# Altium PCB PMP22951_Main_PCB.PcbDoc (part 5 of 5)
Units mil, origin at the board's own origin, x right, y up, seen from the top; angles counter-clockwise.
Board outline 6643.5 x 4153.54 mil, 6 copper layers (Top Layer, Signal Layer 1, Signal Layer 2, Signal Layer 3, Signal Layer 4, Bottom Layer), stack 65.8 mil thick; 139 components, 80 nets, 687 pads, 417 vias.
Unrouted connection lines stored in the file: 2.
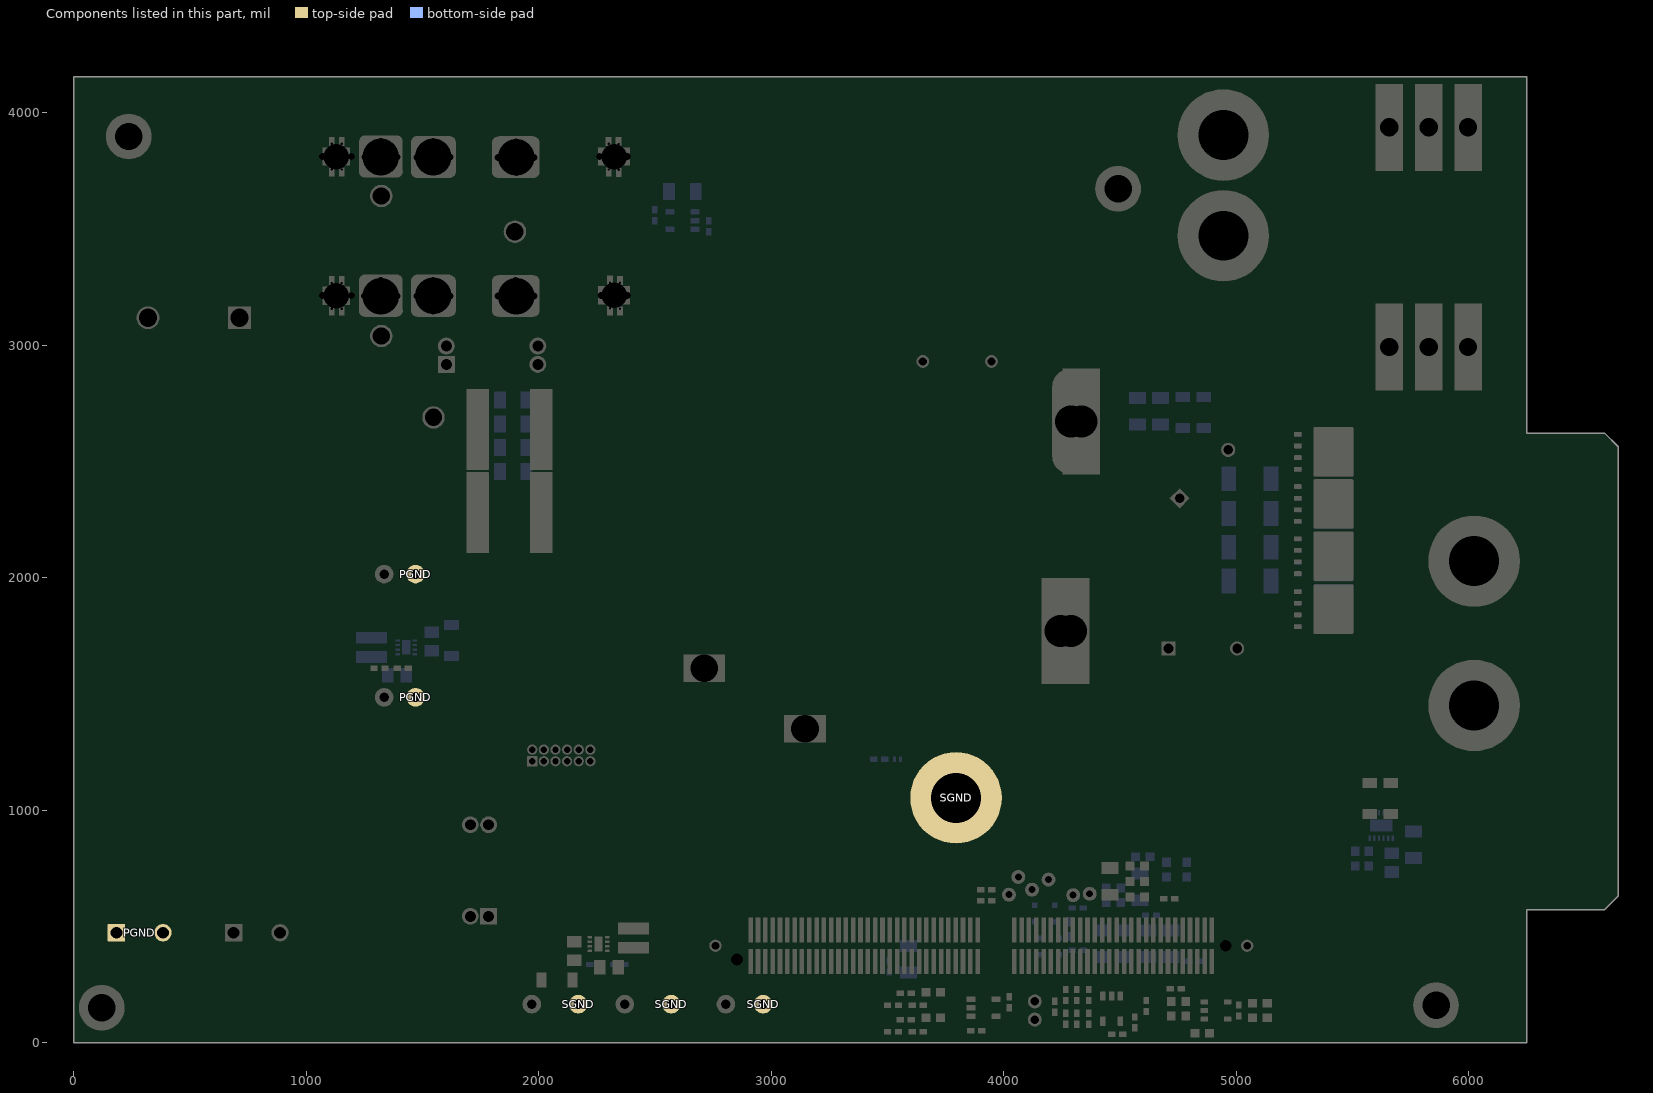
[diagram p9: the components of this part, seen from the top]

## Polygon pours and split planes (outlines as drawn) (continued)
SWNODE2 on Signal Layer 2 "SWNODE2" (solid, remove dead copper, pour order 752): 1236.22,3307.09 1220.47,3291.34 1220.47,3039.37 1283.46,2976.38 1354.33,2976.38 1417.32,3039.37 1417.32,3291.34 1401.57,3307.09
SWNODE1 on Signal Layer 2 "SWNODE1" (solid, remove dead copper, pour order 740): 1236.22,3913.39 1220.47,3897.64 1220.47,3645.67 1283.46,3582.68 1354.33,3582.68 1417.32,3645.67 1417.32,3897.64 1401.57,3913.39
VBB1 on Signal Layer 2 "VBB1" (solid, remove dead copper, pour order 728): 1811.02,3917.32 1771.65,3877.95 1771.65,3141.73 1811.02,3102.36 1984.25,3102.36 2023.62,3141.73 2023.62,3877.95 1984.25,3917.32
SWNODE3 on Signal Layer 2 "SWNODE3" (solid, remove dead copper, pour order 704): 5546.38,4123.43 5561.38,4138.43 5711.38,4138.43 5726.38,4123.43 5726.38,3553.43 5906.38,3373.43 5906.38,2818.43 5886.38,2798.43 5776.38,2798.43 5756.38,2818.43 5756.38,3243.62 5546.38,3453.62
SWNODE4 on Signal Layer 2 "SWNODE4" (solid, remove dead copper, pour order 702): 5921.38,4123.43 5906.38,4138.43 5756.38,4138.43 5741.38,4123.43 5741.38,3563.43 5921.38,3383.43 5921.38,2818.43 5941.38,2798.43 6056.38,2798.43 6076.38,2818.43 6076.38,3593.43 5921.38,3748.43
SWNODE4 on Signal Layer 2 "SWNODE4" (solid, remove dead copper, pour order 700): 5726.38,3177.17 5724.41,3179.13 5724.41,3255.91 5531.5,3448.82 5531.5,3566.93 5433.07,3665.35 4771.65,3665.35 4748.03,3641.73 4748.03,3299.21 4771.65,3275.59 5326.77,3275.59 5338.58,3263.78 5338.58,3050.65 5605.56,2783.43 5706.38,2783.43 5726.38,2803.43
VSR on Signal Layer 2 "VSR" (solid, remove dead copper, pour order 630): 3335,2050 3160,1875 3160,1445 3170,1435 4250,1435 4409.45,1594.45 4409.45,2007.87 4367.32,2050
Iout_SNS on Signal Layer 2 "Iout_SNS" (solid, remove dead copper, pour order 626): 4854.33,2488.19 4905.51,2488.19 4929.13,2464.57 4929.13,1858.27 4724.41,1653.54 4645.67,1653.54 4515.75,1783.46 4515.75,2062.99 4334.65,2244.09 4114.17,2464.57 4114.17,2759.84 4259.84,2905.51 4437.01,2905.51
SGND on Signal Layer 2 "SGND" (solid, remove dead copper, pour order 256): 4860,1095 4880,1075 5134.06,1075 5444.88,1385.83 5500,1385.83 5500,1708.66 5452.76,1708.66 5417.32,1744.09 5125.98,1744.09 5102.36,1767.72 5102.36,2586.61 5047.24,2641.73 4905.51,2641.73 4885.83,2622.05 4885.83,2527.56 4940.94,2472.44 4940.94,1854.33 4860,1773.39
54V1 on Signal Layer 2 "54V1" (solid, remove dead copper, pour order 156): 5122.05,2633.86 5110.24,2622.05 5110.24,1779.53 5129.92,1759.84 5267.72,1759.84 5287.4,1779.53 5287.4,2622.05 5275.59,2633.86
54V2 on Signal Layer 2 "54V2" (solid, remove dead copper, pour order 140): 6228.35,1759.84 6244.09,1775.59 6244.09,2645.67 6224.41,2665.35 5350.39,2665.35 5330.71,2645.67 5330.71,1779.53 5350.39,1759.84
SGND on Signal Layer 2 "SGND" (solid, remove dead copper, pour order 586): 2299.21,1248.03 3515.75,1248.03 3574.8,1188.98 3574.8,755.91 3940.94,755.91 4244.09,1059.05 6192.91,1059.06 6232.28,1019.68 6232.28,35.43 6196.85,0 1910,0 1586.61,0 1559.06,31.5 1559.05,980.32 1724.41,1145.67 1925.2,1346.46 2200.79,1346.46
SGND on Signal Layer 2 "SGND" (solid, remove dead copper, pour order 616): 4255.91,1417.32 4055.12,1417.32 4043.31,1405.51 4043.31,1291.34 4035.43,1283.46 2255.91,1283.46 2255.91,775.59 3937.01,775.59 4240.16,1078.74 4901.57,1078.74 4901.57,1779.53 4889.76,1779.53 4755.91,1645.67 4484.25,1645.67
PGND on Signal Layer 3 "PGND" (solid, remove dead copper, pour order 766): 1062.99,3346.46 944.88,3228.35 633.86,3228.35 606.3,3200.79 606.3,736.22 531.5,661.42 531.5,492.13 433.07,393.7 137.8,393.7 39.37,492.13 39.37,3440.94 145.67,3547.24 1374.02,3547.24 1452.76,3625.98 1452.76,3901.57 1464.57,3913.39 1653.54,3913.39 1669.29,3897.64 1669.29,3125.98 1653.54,3110.24 1472.44,3110.24 1448.82,3133.86 1448.82,3322.83 1425.2,3346.46
SWNODE2 on Signal Layer 3 "SWNODE2" (solid, remove dead copper, pour order 750): 1236.22,3307.09 1220.47,3291.34 1220.47,3039.37 1283.46,2976.38 1354.33,2976.38 1417.32,3039.37 1417.32,3291.34 1401.57,3307.09
SWNODE1 on Signal Layer 3 "SWNODE1" (solid, remove dead copper, pour order 736): 1236.22,3913.39 1220.47,3897.64 1220.47,3645.67 1283.46,3582.68 1354.33,3582.68 1417.32,3645.67 1417.32,3897.64 1401.57,3913.39
VBB1 on Signal Layer 3 "VBB1" (solid, remove dead copper, pour order 726): 1811.02,3917.32 1771.65,3877.95 1771.65,3141.73 1811.02,3102.36 1984.25,3102.36 2023.62,3141.73 2023.62,3877.95 1984.25,3917.32
SWNODE3 on Signal Layer 3 "SWNODE3" (solid, remove dead copper, pour order 706): 5482.91,3308.43 5362.2,3429.13 5362.2,3665.35 5318.9,3708.66 4771.65,3708.66 4748.03,3732.28 4748.03,4078.74 4767.72,4098.43 5519.69,4098.43 5570.87,4047.24 5570.87,3733.11 5590.55,3713.43 5896.38,3713.43 5931.38,3748.43 5931.38,4123.43 5946.38,4138.43 6056.38,4138.43 6146.38,4048.43 6146.38,3438.43 6016.38,3308.43
VSR on Signal Layer 3 "VSR" (solid, remove dead copper, pour order 632): 3335,2050 3160,1875 3160,1445 3170,1435 4250,1435 4409.45,1594.45 4409.45,2007.87 4367.32,2050
Iout_SNS on Signal Layer 3 "Iout_SNS" (solid, remove dead copper, pour order 624): 4854.33,2488.19 4905.51,2488.19 4929.13,2464.57 4929.13,1858.27 4724.41,1653.54 4645.67,1653.54 4515.75,1783.46 4515.75,2066.93 4114.17,2468.5 4114.17,2759.84 4259.84,2905.51 4437.01,2905.51
54V2 on Signal Layer 3 "54V2" (solid, remove dead copper, pour order 138): 6228.35,1759.84 6244.09,1775.59 6244.09,2645.67 6224.41,2665.35 5350.39,2665.35 5330.71,2645.67 5330.71,1779.53 5350.39,1759.84
PGND on Signal Layer 3 "PGND" (solid, remove dead copper, pour order 227): 1640,1140 1260,1140 1180,1139.99 1135,1185 1135,1755 1450,2070 1620,2070 1730,1960 1730,1190 1680,1140
SGND on Signal Layer 3 "SGND" (solid, remove dead copper, pour order 584): 2299.21,1248.03 3515.75,1248.03 3574.8,1188.98 3574.8,933.07 3681.1,826.77 3917.32,826.77 4149.61,1059.06 6192.91,1059.06 6232.28,1019.68 6232.28,35.43 6196.85,0 1910,0 1586.61,0 1559.06,31.5 1559.05,980.32 1724.41,1145.67 1925.2,1346.46 2200.79,1346.46
SGND on Signal Layer 3 "SGND" (solid, remove dead copper, pour order 618): 4255.91,1417.32 4055.12,1417.32 4043.31,1405.51 4043.31,1291.34 4035.43,1283.46 2263.78,1283.46 2263.78,834.65 3913.39,834.65 4153.54,1074.8 5169.29,1074.8 5169.29,1625.98 5062.99,1732.28 4842.52,1732.28 4755.91,1645.67 4484.25,1645.67
SGND on Signal Layer 4 "SGND" (solid, remove dead copper, pour order 790): 2263.78,3976.38 2204.72,3917.32 2204.72,3090.55 2244.09,3051.18 4303.15,3051.18 4940.94,2413.39 4940.94,1830.71 4885.83,1775.59 4885.83,1078.74 4889.76,1074.8 6196.85,1074.8 6244.09,1122.05 6244.09,1732.28 6228.35,1748.03 5125.98,1748.03 5098.43,1775.59 5098.43,2629.92 5145.67,2677.17 6051.18,2677.17 6062.99,2688.98 6062.99,2732.28 6047.24,2748.03 5543.31,2748.03 5283.46,3007.87 5283.46,3181.1 5248.03,3216.54 4696.85,3216.54 4685.04,3228.35 4685.04,4015.75 4566.93,4133.86 2421.26,4133.86
VBB on Signal Layer 4 "VBB" (solid, remove dead copper, pour order 782): 1267.72,2818.9 913.39,3173.23 661.42,3173.23 653.54,3165.35 653.54,2972.44 1019.69,2606.3 1539.37,2086.61 1787.4,2086.61 1811.02,2110.24 1811.02,2795.28 1787.4,2818.9
PGND on Signal Layer 4 "PGND" (solid, remove dead copper, pour order 776): 3059.06,2787.4 3251.97,2980.31 3657.48,2980.31 3688.98,2948.82 3688.98,2846.46 3031.5,2188.98 1830.71,2188.98 1696.85,2322.83 1492.13,2322.83 602.36,1433.07 594.49,1433.07 594.49,3011.81 1011.81,2594.49 1681.1,2594.49 1874.02,2787.4
PGND on Signal Layer 4 "PGND" (solid, remove dead copper, pour order 764): 1062.99,3346.46 944.88,3228.35 633.86,3228.35 606.3,3200.79 606.3,736.22 531.5,661.42 531.5,492.13 433.07,393.7 137.8,393.7 39.37,492.13 39.37,3440.94 145.67,3547.24 1374.02,3547.24 1452.76,3625.98 1452.76,3901.57 1464.57,3913.39 1653.54,3913.39 1669.29,3897.64 1669.29,3125.98 1653.54,3110.24 1472.44,3110.24 1448.82,3133.86 1448.82,3322.83 1425.2,3346.46
SWNODE2 on Signal Layer 4 "SWNODE2" (solid, remove dead copper, pour order 748): 1236.22,3307.09 1220.47,3291.34 1220.47,3039.37 1283.46,2976.38 1354.33,2976.38 1417.32,3039.37 1417.32,3291.34 1401.57,3307.09
SWNODE1 on Signal Layer 4 "SWNODE1" (solid, remove dead copper, pour order 734): 1236.22,3913.39 1220.47,3897.64 1220.47,3645.67 1283.46,3582.68 1354.33,3582.68 1417.32,3645.67 1417.32,3897.64 1401.57,3913.39
VBB1 on Signal Layer 4 "VBB1" (solid, remove dead copper, pour order 724): 1811.02,3917.32 1771.65,3877.95 1771.65,3141.73 1811.02,3102.36 1984.25,3102.36 2023.62,3141.73 2023.62,3877.95 1984.25,3917.32
SWNODE3 on Signal Layer 4 "SWNODE3" (solid, remove dead copper, pour order 712): 5546.38,4123.43 5561.38,4138.43 5711.38,4138.43 5726.38,4123.43 5726.38,3553.43 5906.38,3373.43 5906.38,2818.43 5886.38,2798.43 5776.38,2798.43 5756.38,2818.43 5756.38,3243.62 5546.38,3453.62
SWNODE4 on Signal Layer 4 "SWNODE4" (solid, remove dead copper, pour order 710): 5921.38,4123.43 5906.38,4138.43 5756.38,4138.43 5741.38,4123.43 5741.38,3563.43 5921.38,3383.43 5921.38,2818.43 5941.38,2798.43 6056.38,2798.43 6076.38,2818.43 6076.38,3593.43 5921.38,3748.43
SWNODE4 on Signal Layer 4 "SWNODE4" (solid, remove dead copper, pour order 708): 5726.38,3177.17 5724.41,3179.13 5724.41,3255.91 5531.5,3448.82 5531.5,3566.93 5433.07,3665.35 4771.65,3665.35 4748.03,3641.73 4748.03,3299.21 4771.65,3275.59 5326.77,3275.59 5338.58,3263.78 5338.58,3050.65 5605.56,2783.43 5706.38,2783.43 5726.38,2803.43
VSR on Signal Layer 4 "VSR" (solid, remove dead copper, pour order 634): 3335,2050 3160,1875 3160,1445 3170,1435 4250,1435 4409.45,1594.45 4409.45,2007.87 4367.32,2050
Iout_SNS on Signal Layer 4 "Iout_SNS" (solid, remove dead copper, pour order 622): 4854.33,2488.19 4905.51,2488.19 4929.13,2464.57 4929.13,1858.27 4724.41,1653.54 4645.67,1653.54 4637.8,1661.42 4637.8,2110.24 4503.94,2244.09 4437.01,2244.09 4196.85,2484.25 4196.85,2842.52 4259.84,2905.51 4437.01,2905.51
54V1 on Signal Layer 4 "54V1" (solid, remove dead copper, pour order 152): 5122.05,2633.86 5110.24,2622.05 5110.24,1779.53 5129.92,1759.84 5267.72,1759.84 5287.4,1779.53 5287.4,2622.05 5275.59,2633.86
54V2 on Signal Layer 4 "54V2" (solid, remove dead copper, pour order 136): 6228.35,1759.84 6244.09,1775.59 6244.09,2645.67 6224.41,2665.35 5350.39,2665.35 5330.71,2645.67 5330.71,1779.53 5350.39,1759.84
PGND on Signal Layer 4 "PGND" (solid, remove dead copper, pour order 226): 1640,1140 1260,1140 1180,1139.99 1135,1185 1135,1755 1450,2070 1620,2070 1730,1960 1730,1190 1680,1140
SGND on Signal Layer 4 "SGND" (solid, remove dead copper, pour order 582): 2244.09,1344.49 2248.03,1340.55 2248.03,1248.03 3515.75,1248.03 3515.75,759.84 4023.62,759.84 4322.83,1059.06 6232.28,1059.06 6232.28,35.43 6196.85,0 1910,0 1586.61,0 1559.06,31.5 1559.05,980.32 1724.41,1145.67 1925.2,1346.46 2200.79,1346.46 2202.76,1344.49
SGND on Signal Layer 4 "SGND" (solid, remove dead copper, pour order 620): 4248.03,1417.18 4047.24,1417.18 4035.43,1405.37 4035.43,1291.2 4027.56,1283.33 3133.86,1283.33 3133.86,775.45 4015.61,775.45 4318.76,1078.6 4897.64,1078.6 4897.64,1763.64 4866.14,1763.64 4748.03,1645.53 4476.38,1645.53

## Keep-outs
Keep-Out Layer:
  text ".Layer_Name" at 577,-858.49 h60

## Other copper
Top Layer:
  region: 6402.99,674.53 6402.99,643.03 6599.84,643.03 6599.84,674.33
  region: 6402.99,724.53 6402.99,693.03 6599.84,693.03 6599.84,724.53
  region net PSFB_ON: 6402.99,774.53 6599.84,774.53 6599.84,743.03 6402.99,743.03
  region net 54VLS-EN: 6402.99,824.53 6402.99,793.03 6599.84,793.03 6599.84,824.53
  region: 6402.99,874.53 6402.99,843.03 6599.84,843.03 6599.84,874.53
  region net Vout_SNS-: 6402.99,924.53 6402.99,893.03 6599.84,893.03 6599.84,924.53
  region net Vout_SNS+: 6402.99,974.53 6402.99,943.03 6599.84,943.03 6599.84,974.53
  region: 6402.99,1024.53 6402.99,993.03 6599.84,993.03 6599.84,1024.53
  region: 6402.99,1074.53 6402.99,1043.03 6599.84,1043.03 6599.84,1074.53
  region: 6402.99,1124.53 6402.99,1093.03 6598.46,1093.03 6599.84,1091.65 6599.84,1124.53
  region net SGND: 6305.12,1782.68 6600.39,1782.68 6600.39,1610.24 6305.12,1610.24
  region net 54V2: 6304.57,2182.8 6599.84,2182.8 6599.84,2010.35 6304.57,2010.35
  region net 54V2: 6304.57,2582.8 6599.84,2582.8 6599.84,2210.35 6304.57,2210.35
  region net 54V2: 6304.57,1982.8 6599.84,1982.8 6599.84,1810.35 6304.57,1810.35
  region net SGND: 6303.82,1582.05 6599.09,1582.05 6599.09,1209.61 6303.82,1209.61
  text ".Layer_Name" at 527.56,-113.19 h60
Signal Layer 1:
  pour cut-out: 4900,700 4940,700 4940,660 4900,660
Signal Layer 2:
  pour cut-out: 4900,700 4940,700 4940,660 4900,660
Signal Layer 4:
  pour cut-out: 4900,700 4940,700 4940,660 4900,660
Bottom Layer:
  pour cut-out: 1000,3555.12 1000,3275.59 1043.31,3318.9 1047.24,3318.9 1047.24,3555.12
  region: 6402.24,673.78 6402.24,642.28 6599.09,642.28 6599.09,673.78
  region: 6402.24,723.78 6599.09,723.78 6599.09,692.28 6402.24,692.28
  region: 6402.24,773.78 6599.09,773.78 6599.09,742.28 6402.24,742.28
  region: 6402.24,823.78 6599.09,823.78 6599.09,792.28 6402.24,792.28
  region: 6402.24,873.78 6402.24,842.28 6599.09,842.28 6599.09,873.78
  region: 6402.24,923.78 6599.09,923.78 6599.09,892.28 6402.24,892.28
  region: 6402.24,973.78 6599.09,973.78 6599.09,942.28 6402.24,942.28
  region: 6402.24,1023.78 6402.24,992.28 6599.09,992.28 6599.09,1023.78
  region: 6402.24,1073.78 6599.09,1073.78 6599.09,1042.28 6402.24,1042.28
  region: 6402.24,1123.78 6599.09,1123.78 6599.09,1092.28 6402.24,1092.28
  region net SGND: 6303.82,1782.05 6599.09,1782.05 6599.09,1609.61 6303.82,1609.61
  region net 54V2: 6303.82,2182.05 6599.09,2182.05 6599.09,2009.61 6303.82,2009.61
  region net SGND: 6303.82,1982.05 6598.11,1982.05 6599.09,1981.06 6599.09,1809.61 6303.82,1809.61
  region net 54V2: 6303.82,2582.05 6599.09,2582.05 6599.09,2209.61 6303.82,2209.61
  region net SGND: 6303.82,1582.05 6599.09,1582.05 6599.09,1209.61 6303.82,1209.61
  text ".Layer_Name" at 577,-858.49 h60

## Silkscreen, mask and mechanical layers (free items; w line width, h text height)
Top Overlay:
  lines w7.01: 5336.38,4261.85 6320.63,4261.85 ; 1779.33,1269.21 1779.33,1426.69 3991.85,1426.69 3991.85,1269.21 1779.33,1269.21 ; 2075,1080 2075,2812.28 4909.65,2812.28 4909.65,1080 2075,1080 ; 2075,1545 3795,1545 3795,2952.76 2075,2952.76 2075,1545
  lines w7.87: 123.82,1012.6 1226.18,1012.6 1226.18,2587.4 123.82,2587.4 123.82,1012.6
  lines w10: 2070,1300 2590,1300 ; 2070,1350 2590,1350 ; 2279.25,850 2282.32,1660 ; 2712.32,1259.84 2712.32,1665 ; 2935,1250 2935,2600 ; 3145.39,1259.84 3145.39,1685 ; 3578.46,880 3578.46,1690 ; 4015.75,811.02 4019.69,807.09 4019.69,751.97 ; 4051.18,665.35 4082.68,696.85 4082.68,791.34 4118.11,826.77 4200.79,826.77 ; 4114.17,700.79 4114.17,759.84 4141.73,787.4 4196.85,787.4 ; 4228.35,692.91 4232.28,692.91 4248.03,708.66 ; 4574.8,803.15 4614.17,842.52 4751.97,842.52 ; 4748.03,3667.6 5338.58,3667.6 ; 4748.03,3706.97 5338.58,3706.97 ; 4748.03,4100.67 5338.58,4100.67 5338.58,4240.16 6295.28,4240.16 ; 5062.99,3465 6311.02,3465 ; 5062.99,3687.28 5417.32,3687.28 ; 5236.22,133.86 5338.58,133.86 5385.83,181.1 5385.83,255.91 ; 6224.41,566.93 6224.41,594.49 5338.58,594.49 5275.59,531.5 5275.59,314.96 5334.65,255.91 5748.03,255.91 5779.53,287.4 6161.42,287.4 6224.41,350.39 6224.41,590.55 ; 1543.31,2858.27 1543.31,3055.12 2055.12,3055.12 2055.12,2858.27 1543.31,2858.27
  text "Place holder for fan" at 350,2420 h90
  text "Slot for XFMR Card" at 2318.9,1696.85 h72.83
  text "Slot for SR Card" at 2695,1175 h72.83
  text "LEG2_LS" at 4141.73,838.58 h47.24
  text "LEG2_HS" at 3913.39,834.65 h47.24
  text "LEG1_LS" at 4212.6,783.46 h47.24
  text "LEG1_HS" at 4212.6,740.16 h47.24
  text "–" at 417.32,204.72 h118.11
  text "+" at 952.76,192.91 h118.11
  text "PMP22951 Main RevE" at 299.21,74.8 h72.83
  text ".Layer_Name" at 577,-858.49 h60
Bottom Overlay:
  lines w7.01: 3163.15,1448.15 3556.85,1448.15 3556.85,1841.85 3163.15,1841.85 3163.15,1448.15
  lines w10: 4035.43,755.91 4125.98,755.91 4141.73,740.16 4141.73,692.91 4169.29,665.35 4224.41,665.35 ; 4225,665 4250,640 ; 4287.4,720.47 4290,680 ; 4320,315 4320,375 ; 4640,660 4650,660 4665,645 4685,625 4715,625 ; 4805,3035 4805,3010 4820,2995 4890,2995 4950,2935 4950,2865 ; 4810,545 4825,545 4850,520 4850,460 4895,415 4895,370 4915,350 4935,350 ; 5015,470 5025,460 5075,460 5100,435 5100,370
  text "IHV_FB" at 4393.7,748.03 h72.83
  text ".Layer_Name" at 577,-858.49 h60
Top Paste:
  text ".Layer_Name" at 577,-858.49 h60
Bottom Paste:
  rectangle: 5527.56,1767.72 5807.09,2633.86
  text ".Layer_Name" at 577,-858.49 h60
Top Solder:
  region: 4748.03,4098.43 4748.03,3271.65 5318.9,3271.65 5318.9,4098.43
  rectangle: 5527.56,1771.65 5799.21,2641.73
  rectangle: 3745.43,3672.68 4035.43,4082.68
  rectangle: 3383.23,3438.86 3673.23,3633.86
  rectangle: 6346.46,622.05 6614.17,2602.36
  text ".Layer_Name" at 577,-858.49 h60
  text ".Layer_Name" at 577,-858.49 h60
Bottom Solder:
  rectangle: 1783.46,2153.54 1866.14,2397.64
  rectangle: 1909.45,2153.54 1992.13,2397.64
  region: 4748.03,4102.36 4748.03,3271.65 5318.9,3271.65 5318.9,4102.36
  rectangle: 3750.43,3688.74 4035.43,4078.74
  rectangle: 4144.06,1521.06 4389.06,2016.06
  rectangle: 4189.06,2421.06 4439.06,2916.06
  rectangle: 3165,1450 3555,2039.37
  rectangle: 3370.94,3428.54 3685.04,3653.54
  rectangle: 2825,2815 3255,2915
  rectangle: 6334.65,614.17 6618.11,2602.36
  text ".Layer_Name" at 577,-858.49 h60
Drill Guide:
  text ".Layer_Name" at 577,-858.49 h60
M1 Board Outline:
  the board outline again, w10
  text ".Layer_Name" at 577,-858.49 h60
M2 Board Dimensions:
  rectangle: 125,-400 500,-275
  rectangle: 0,-275 125,-150
  lines w7: 0,-275 1000,-275 ; 125,-400 125,-150 ; 250,-400 250,-150 ; 500,-400 500,-150 ; 750,-400 750,-150 ; 0,-400 0,-150 1000,-150 1000,-400 0,-400
  text ".Layer_Name" at 577,-858.49 h60
M3 3D STEP Top:
  text ".Layer_Name" at 577,-858.49 h60
M4 3D STEP Bottom:
  text ".Layer_Name" at 577,-858.49 h60
M5 Assembly Top:
  lines w10: -292,-930.17 6308,-930.17 ; -292,-726.83 6310,-726.83 ; -292,-523.5 -292,-1133.5 3713,-1133.5 6310,-1133.5 6310,-523.5 -291.5,-523.5 -291.5,-1133.5 1284,-1133.5 ; 2173,-1133.5 2173,-523.5 ; 3440,-726.83 3440,-523.5 ; 4280,-726.83 4280,-523.5 ; 4902,-1140 4902,-937.17
  text "COMPONENTS MARKED 'DNP' SHOULD NOT BE POPULATED." at 1153.5,-318.5 h60
  text "ASSEMBLY VARIANT:" at 1153,-434 h60
  text ".VariantName" at 2189,-434 h60
  text "PCB VIEWED FROM TOP SIDE" at -228.5,-655.67 h60
  text "BOARD #:" at 2248,-655.67 h60
  text ".PRJ_Number" at 2793.5,-655.67 h60
  text "REV:" at 3638,-655.67 h60
  text ".PCB_Rev" at 3929.5,-655.67 h60
  text "SVN REV:" at 4476,-655.67 h60
  text ".VersionControl_RevNumber" at 4982,-655.67 h60
  text "TID #:" at 2248,-859 h60
  text ".TID" at 2793.5,-859 h60
  text "PLOT NAME =" at -228.5,-1064.34 h60
  text ".plot_File_Name" at 577,-1064.34 h60
  text "GENERATED    :" at 2250,-1064.34 h60
  text ".Print_Date" at 3119.5,-1064.34 h60
  text ".Print_Time" at 3848.5,-1064.34 h60
  text "TEXAS INSTRUMENTS" at 5113,-1064.34 h60
M6 Assembly Bottom:
  lines w10: -292.5,-727.33 6309.5,-727.33 ; -290.5,-930.67 6309.5,-930.67 ; 1115.5,-1140.5 1115.5,-937.67 ; 1737.5,-727.33 1737.5,-524 ; 2577.5,-727.33 2577.5,-524 ; 3844.5,-1134 3844.5,-524 ; 4733.5,-1134 6309,-1134 6309,-524 -292.5,-524 -292.5,-1134 2304.5,-1134 6309.5,-1134 6309.5,-524
  text "COMPONENTS MARKED 'DNP' SHOULD NOT BE POPULATED." at 6853.97,-314.06 h60
  text ".VariantName" at 5058,-434 h60
  text "ASSEMBLY VARIANT:" at 6097,-434 h60
  text ".VersionControl_RevNumber" at 1035.5,-656.17 h60
  text "SVN REV:" at 1541.5,-656.17 h60
  text ".PCB_Rev" at 2088,-656.17 h60
  text "REV:" at 2379.5,-656.17 h60
  text ".PRJ_Number" at 3224,-656.17 h60
  text "BOARD #:" at 3769.5,-656.17 h60
  text "PCB VIEWED FROM BOTTOM SIDE" at 6246,-656.17 h60
  text ".TID" at 3224,-859.5 h60
  text "TID #:" at 3769.5,-859.5 h60
  text "TEXAS INSTRUMENTS" at 904.5,-1064.84 h60
  text ".Print_Time" at 2169,-1064.84 h60
  text ".Print_Date" at 2898,-1064.84 h60
  text "GENERATED    :" at 3767.5,-1064.84 h60
  text ".plot_File_Name" at 5440.5,-1064.84 h60
  text "PLOT NAME =" at 6246,-1064.84 h60
M9 Title Sheet:
  drawing of 57 lines, arcs and shapes, not listed
  text "1" at 739.84,8036.5 h70
  text "2" at 3235.5,8036.5 h70
  text "3" at 5724.84,8036.5 h70
  text "4" at 8231.51,8036.5 h70
  text "5" at 10730.5,8036.5 h70
  text "6" at 13235.5,8036.5 h70
  text "A" at -416.5,6893.5 h70
  text "A" at 14383.5,6893.5 h70
  text "B" at -416.5,4513.5 h70
  text "B" at 14383.5,4513.5 h70
  text "C" at -416.5,2138.5 h70
  text "C" at 14383.5,2138.5 h70
  text "PROJECT TITLE:" at 11343.5,277.5 h45
  text ".PRJ_Title" at 11393.5,144.17 h70
  text "DESIGNED FOR:" at 11343.5,-23.5 h45
  text ".PRJ_Customer" at 11393.5,-163.5 h70
  text "D" at -416.5,-231.5 h70
  text "D" at 14383.5,-231.5 h70
  text "FILE NAME:" at 11343.5,-323.5 h45
  text ".PCB_File_Name_No_Path" at 11393.5,-443.5 h70
  text "Texas Instruments (TI) and/or its licensors do not warrant the accuracy or completeness of this specification" at 6374,-605.34 h45
  text "ENGINEER:" at 11343.5,-613.5 h45
  text "LAYOUT BY:" at 12848.5,-613.5 h45
  text "or any information contained therein. TI and/or its licensors do not warrant that this design will meet" at 6329.01,-718 h45
  text ".PRJ_Engineer" at 11393.5,-768.49 h70
  text ".PCB_Layout" at 12899,-768.49 h70
  text "the specifications, will be suitable for your application or fit for any particular purpose, or will operate in" at 6329.01,-830.67 h45
  text ".Layer_Name" at 577,-858.49 h60
  text "ALTIUM DESIGNER VERSION:" at 12848.5,-923.5 h45
  text "an implementation. TI and/or its licensors do not warrant that the design is production worthy. You should" at 6329.01,-943.33 h45
  text "completely validate and test your design implementation to confirm the system functionality for your application." at 6374,-1056 h45
  text ".print_Scale" at 11393.5,-1056.83 h70
  text ".Application_BuildNumber" at 12899,-1056.83 h70
  text "1" at 739.84,-1263.5 h70
  text "2" at 3235.5,-1263.5 h70
  text "3" at 5724.84,-1263.5 h70
  text "4" at 8231.51,-1263.5 h70
  text "5" at 10730.5,-1263.5 h70
  text "6" at 13235.5,-1263.5 h70
M10 Fab Notes:
  drawing of 189 lines, arcs and shapes, not listed
  text "DESIGN INFORMATION" at 12382.02,6356.17 h60
  text "MIN. TRACK WIDTH:" at 11737.46,6224.05 h60
  text "8" at 12833.7,6224.05 h60
  text "MIL" at 12988.46,6224.05 h60
  text "MIN. CLEARANCE:" at 11737.46,6099.92 h60
  text "0.2" at 12773.7,6099.93 h60
  text "mm" at 12988.46,6099.92 h60
  text "MIN. VIA PAD SIZE:" at 11737.46,5975.8 h60
  text "20" at 12803.71,5975.8 h60
  text "MIL" at 12988.46,5975.8 h60
  text "0.05mm (2MIL)" at 12432.46,5845.9 h60
  text "MINIMUM ANNULAR RING" at 11408.23,5837.67 h60
  text "EXTERNAL" at 13140.46,5837.67 h60
  text "PER" at 11608.23,5727.55 h60
  text "IPC-D-275 CLASS 2 LEVEL C" at 11828.23,5727.54 h60
  text "MIL, HOLES" at 13316.46,5627.07 h60
  text "+/-" at 12924,5618.48 h60
  text "+/-" at 13778,5618.48 h60
  text "REGISTRATION TOLERANCES:" at 11408.23,5617.42 h60
  text "METAL" at 12608,5617.42 h60
  text "5" at 13184.2,5617.42 h60
  text "3" at 14017.2,5617.42 h60
  text "MIL" at 14133.46,5617.42 h60
  text "HOLE SIZE TOLERANCE (UNLESS OTHERWISE SPECIFIED):" at 11408.23,5519.1 h60
  text "+/-" at 13778,5516.23 h60
  text "3" at 14017.2,5515.17 h60
  text "MIL" at 14133.46,5515.17 h60
  text "MATERIAL:" at 11333.46,5377.52 h60
  text "FR-4 High Tg" at 12319.9,5249 h60
  text "X" at 12175.46,5241.01 h60
  text "FR-408" at 11754.46,5236.49 h60
  text "OTHER" at 13242.46,5236.49 h60
  text "62 MIL (1.6mm) +/-10%" at 12074.56,5093.46 h60
  text "X" at 11954.46,5091.01 h60
  text "THICKNESS:" at 11408.23,5085.24 h60
  text "OTHER" at 13359.46,5085.24 h60
  text "TOLERANCE:" at 11408.23,4946.92 h60
  text "X" at 12256.46,4946.92 h60
  text "ANSI IPC-6012 TYPE 3 CLASS 2" at 12434.48,4946.92 h60
  text "OTHER +/-" at 12434.46,4802.73 h60
  text "BOW & TWIST:" at 11408.23,4657.54 h60
  text "X" at 12256.46,4657.54 h60
  text "ANSI IPC-6012 TYPE 3 CLASS 2" at 12434.48,4657.54 h60
  text "OTHER +/-" at 12434.46,4510.85 h60
  text "DRILLING:" at 11333.46,4380.23 h60
  text "NC_DRILL FILES" at 13094.46,4275.04 h60
  text "REFERENCE:" at 11408.23,4271.1 h60
  text "X" at 12065.46,4271.01 h60
  text "AS SHOWN" at 12243.46,4271.1 h60
  text "X" at 12966.46,4271.1 h60
  text "OTHER" at 13392.46,4128.85 h60
  text "PTH COPPER THICKNESS:" at 11407.91,4125.32 h60
  text "X" at 12547.14,4125.32 h60
  text "20-30 um" at 12675.14,4125.32 h60
  text "BOARD FINISH:" at 11333.46,3977.73 h60
  text "SILKSCREEN:" at 11488.68,3867.6 h60
  text "X" at 12446.46,3867.6 h60
  text "TOP" at 12563.46,3867.6 h60
  text "X" at 12956.46,3867.6 h60
  text "BOTTOM" at 13074.46,3867.6 h60
  text "SILKSCREEN COLOR:" at 11488.68,3712.41 h60
  text "X" at 12445.46,3712.41 h60
  text "WHITE" at 12563.46,3712.41 h60
  text "OTHER" at 13074.46,3712.41 h60
  text "X" at 12576.46,3568.96 h60
  text "GREEN" at 12694.46,3568.96 h60
  text "OTHER" at 13312.46,3568.96 h60
  text "SOLDER RESIST COLOR:" at 11488.68,3562.1 h60
  text "X" at 12576.46,3414.71 h60
  text "MATTE" at 12694.46,3414.71 h60
  text "SEMI-GLOSS" at 13312,3414.07 h60
  text "IMMERSION GOLD (ENIG)" at 12394.46,3241.94 h60
  text "ENEPIG" at 13732,3234.72 h60
  text "SURFACE FINISH:" at 11333.46,3233.72 h60
  text "X" at 12216.46,3233.72 h60
  text "IMM. TIN/SILVER OR EQUIV" at 11663,3096.4 h60
  text "OTHER" at 13094.46,3092.47 h60
  text "ARRAY/PANEL:" at 11333.46,2937.09 h60
  text "CUT AND TRIM PER M1 BOARD OUTLINE" at 12394.46,2928.87 h60
  text "N.C. ROUTE" at 12394.46,2792.9 h60
  text "X" at 13082.46,2792.9 h60
  text "V. SCORE" at 13260.46,2792.9 h60
  text "CERTIFICATION:" at 11333.46,2663.77 h60
  text "MATERIALS AND WORKMANSHIP FOR ALL PCBS" at 12058.46,2663.77 h60
  text "TO MEET OR EXCEED THE REQUIREMENTS OF:" at 12058.46,2569.71 h60
  text "X" at 11695.97,2441.08 h60
  text "ANSI IPC-A-600F CLASS ->" at 11823.96,2441.08 h60
  text "X" at 13471.97,2441.08 h60
  text "2" at 13581.96,2441.08 h60
  text "1" at 13266.96,2439.58 h60
  text "3" at 13935.96,2439.58 h60
  text "X" at 12507.97,2293.39 h60
  text "RoHS" at 12635.96,2293.39 h60
  text "OTHER" at 13280.36,2293.39 h60
  text "PER ORDER" at 13677.42,2293.39 h60
  text "ALL BOARDS MUST MEET OR EXCEED UL94-V0 REQUIREMENTS." at 11361,2139.57 h60
  text "PCB MUST BEAR THE UL94V-0 UL REGISTERED MATERIAL ID NUMBER" at 11361,2023.5 h60
  text "ADDITIONAL REQUIREMENTS:" at 11333.46,1854.08 h60
  text "MICROSECTION:" at 11408.23,1746.95 h60
  text "YES" at 12313.96,1746.95 h60
  text "REQUIRED" at 13175.46,1602.62 h60
  text "BARE BOARD ELEC. TEST:" at 11408.23,1599.76 h60
  text "NONE" at 12713.96,1599.76 h60
  text "X" at 13057.46,1599.76 h60
  text "PER ORDER" at 13767.46,1599.76 h60
  text "XX MIL VIAS REQUIRE NON-CONDUCTIVE FILL AND PLANARIZE" at 11576.38,1394.82 h59
  text "XX MIL VIAS REQUIRE CONDUCTIVE FILL AND PLANARIZE" at 11584.38,1290.84 h60
  text "OUTER XX MIL TRACES REQUIRE 50 OHM SINGLE-ENDED IMPEDANCE" at 11583.39,1127.46 h58
  text "LAYER 2 & 3 (INNER LAYERS) XX MIL WIDE, XX MIL SPACE / TRACES REQUIRE 100 OHM DIFFERENTIAL IMPEDANCE" at 11575.39,891.74 h60
  text ".Layer_Name" at 577,-858.49 h60
M11 Gerber Information:
  lines w10: -292,-930.17 6308,-930.17 ; -292,-726.83 6310,-726.83 ; -292,-523.5 -292,-1133.5 3713,-1133.5 6310,-1133.5 6310,-523.5 -291.5,-523.5 -291.5,-1133.5 1284,-1133.5 ; 2173,-1133.5 2173,-523.5 ; 3440,-726.83 3440,-523.5 ; 4280,-726.83 4280,-523.5 ; 4902,-1140 4902,-937.17
  text "ALL ARTWORK VIEWED FROM TOP SIDE" at -228.5,-655.67 h60
  text "BOARD #:" at 2248,-655.67 h60
  text ".PRJ_Number" at 2793.5,-655.67 h60
  text "REV:" at 3638,-655.67 h60
  text ".PCB_Rev" at 3929.5,-655.67 h60
  text "SVN REV:" at 4476,-655.67 h60
  text ".VersionControl_RevNumber" at 4982,-655.67 h60
  text "LAYER NAME =" at -228.5,-858.49 h60
  text "TID #:" at 2248,-859 h60
  text ".TID" at 2793.5,-859 h60
  text "PLOT NAME =" at -228.5,-1064.34 h60
  text ".plot_File_Name" at 577,-1064.34 h60
  text "GENERATED    :" at 2250,-1064.34 h60
  text ".Print_Date" at 3119.5,-1064.34 h60
  text ".Print_Time" at 3848.5,-1064.34 h60
  text "TEXAS INSTRUMENTS" at 5113,-1064.34 h60
M12 Stackup:
  drawing of 399 lines, arcs and shapes, not listed
  text "Layer" at 6715.09,7732.5 h60
  text "Name" at 7125,7732.5 h60
  text "Material" at 8064.74,7732.5 h60
  text "Thickness" at 8924.51,7732.5 h60
  text "Constant" at 9574.34,7732.5 h60
  text "Board Layer Stack" at 10144.2,7732.5 h60
  text "1" at 6715.09,7612.5 h60
  text "Top Overlay" at 7125,7612.5 h60
  text "2" at 6715.09,7492.5 h60
  text "Top Solder" at 7125,7492.5 h60
  text "Solder Resist" at 8064.74,7492.5 h60
  text "0.40mil" at 8924.51,7492.5 h60
  text "3.5" at 9574.34,7492.5 h60
  text "3" at 6715.09,7372.5 h60
  text "Top Layer" at 7125,7372.5 h60
  text "Copper" at 8064.74,7372.5 h60
  text "2.80mil" at 8924.51,7372.5 h60
  text "4" at 6715.09,7252.5 h60
  text "Dielectric 2" at 7125,7252.5 h60
  text "7.00mil" at 8924.51,7252.5 h60
  text "4.2" at 9574.34,7252.5 h60
  text "5" at 6715.09,7132.5 h60
  text "Signal Layer 1" at 7125,7132.5 h60
  text "Copper" at 8064.74,7132.5 h60
  text "2.80mil" at 8924.51,7132.5 h60
  text "6" at 6715.09,7012.5 h60
  text "Dielectric 3" at 7125,7012.5 h60
  text "14.00mil" at 8924.51,7012.5 h60
  text "4.2" at 9574.34,7012.5 h60
  text "7" at 6715.09,6892.5 h60
  text "Signal Layer 2" at 7125,6892.5 h60
  text "Copper" at 8064.74,6892.5 h60
  text "2.80mil" at 8924.51,6892.5 h60
  text "8" at 6715.09,6772.5 h60
  text "Dielectric1" at 7125,6772.5 h60
  text "FR-4" at 8064.74,6772.5 h60
  text "7.00mil" at 8924.51,6772.5 h60
  text "4.2" at 9574.34,6772.5 h60
  text "9" at 6715.09,6652.5 h60
  text "Signal Layer 3" at 7125,6652.5 h60
  text "Copper" at 8064.74,6652.5 h60
  text "2.80mil" at 8924.51,6652.5 h60
  text "10" at 6715.09,6532.5 h60
  text "Dielectric 4" at 7125,6532.5 h60
  text "14.00mil" at 8924.51,6532.5 h60
  text "4.2" at 9574.34,6532.5 h60
  text "11" at 6715.09,6412.5 h60
  text "Signal Layer 4" at 7125,6412.5 h60
  text "Copper" at 8064.74,6412.5 h60
  text "2.80mil" at 8924.51,6412.5 h60
  text "12" at 6715.09,6292.5 h60
  text "Dielectric 5" at 7125,6292.5 h60
  text "7.00mil" at 8924.51,6292.5 h60
  text "4.2" at 9574.34,6292.5 h60
  text "13" at 6715.09,6172.5 h60
  text "Bottom Layer" at 7125,6172.5 h60
  text "Copper" at 8064.74,6172.5 h60
  text "2.80mil" at 8924.51,6172.5 h60
  text "14" at 6715.09,6052.5 h60
  text "Bottom Solder" at 7125,6052.5 h60
  text "Solder Resist" at 8064.74,6052.5 h60
  text "0.40mil" at 8924.51,6052.5 h60
  text "3.5" at 9574.34,6052.5 h60
  text "15" at 6715.09,5932.5 h60
  text "Bottom Overlay" at 7125,5932.5 h60
  text ".Layer_Name" at 577,-858.49 h60
M13 Component Bodies Top:
  text ".Layer_Name" at 577,-858.49 h60
M14 Component Bodies Bottom:
  text ".Layer_Name" at 577,-858.49 h60
M15 Courtyards Top:
  text ".Layer_Name" at 577,-858.49 h60
M16 Courtyards Bottom:
  text ".Layer_Name" at 577,-858.49 h60
Drill Drawing:
  text ".Layer_Name" at 577,-858.49 h60
M17 Embedded Cavity:
  text ".Layer_Name" at 577,-858.49 h60
M18 Embedded Assembly:
  text ".Layer_Name" at 577,-858.49 h60
M19 Embedded Keepout:
  text ".Layer_Name" at 577,-858.49 h60

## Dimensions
0,-400 to 1000,-400 on M2 Board Dimensions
